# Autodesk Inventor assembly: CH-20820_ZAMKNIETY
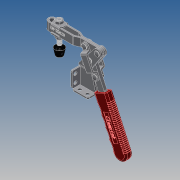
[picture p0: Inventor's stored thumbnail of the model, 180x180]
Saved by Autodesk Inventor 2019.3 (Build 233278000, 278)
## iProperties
Company: Î¢ÈíÖÐ¹ú
Created: 2011-12
Part Number: CH-20820_ZAMKNIETY
Material: Ogólny
Description: STEP AP203
Document SubType Name: Assembly
Designer: CADENGINEERING4
Sending System: SolidWorks 2010
Preprocessor: SwSTEP 2.0
Title: CH-20820.STEP
Author: Î¢ÈíÓÃ»§
Revision Number: ÈÎºÎ
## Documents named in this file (10)
- E:\STRONA\Horizontal toggle clamp\CH-20820\CH-20820_ZAMKNIETY.iam
- E:\STRONA\Horizontal toggle clamp\CH-20820\20820-02.ipt
- E:\STRONA\Horizontal toggle clamp\CH-20820\20820-06.ipt
- E:\STRONA\Horizontal toggle clamp\CH-20820\56212.ipt
- E:\STRONA\Horizontal toggle clamp\CH-20820\20820-03.ipt
- E:\STRONA\Horizontal toggle clamp\CH-20820\FW516.ipt
- E:\STRONA\Horizontal toggle clamp\CH-20820\20820-04.ipt
- E:\STRONA\Horizontal toggle clamp\CH-20820\CH-20820-05.ipt
- E:\STRONA\Horizontal toggle clamp\CH-20820\56212-02.ipt
- E:\STRONA\Horizontal toggle clamp\CH-20820\20820-01.ipt
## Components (15 placed, 15 different names)
1. 20820-02_1 — Zestawiające:1, Zestawiające:4, Zestawiające:6, Zestawiające:9, Zestawiające:24, Zestawiające:25, Zestawiające:28
2. 20820-06_2 — Zestawiające:22, Zestawiające:23
3. 56212_3 — Równoległe:1, Zestawiające:2, Zestawiające:5, Zestawiające:7, Zestawiające:9
4. 20820-06_4 — Zestawiające:28, Zestawiające:29, Zestawiające:30
5. 20820-03_5 — Zestawiające:10, Zestawiające:11, Zestawiające:12, Zestawiające:13, Zestawiające:14, Zestawiające:17, Zestawiające:18, Zestawiające:19, Zestawiające:20
6. FW516_6 — Równoległe:2, Zestawiające:5, Zestawiające:6, Zestawiające:8
7. 20820-04_7 — Zestawiające:19, Zestawiające:20, Zestawiające:21, Zestawiające:22, Zestawiające:23, Zestawiające:24, Zestawiające:25, Zestawiające:26, Zestawiające:27
8. CH-20820-05_8 — Zestawiające:10, Zestawiające:11, Zestawiające:12, Zestawiające:31
9. 56212-02_9 — Równoległe:1, Zestawiające:3
10. 20820-01_10 — Zestawiające:13, Zestawiające:14, Zestawiające:15, Zestawiające:16, Zestawiające:29, Zestawiające:30, Zestawiające:31
11. 20820-06_11 — Zestawiające:15, Zestawiające:16
12. 20820-06_12 — Zestawiające:26, Zestawiające:27
13. FW516_13 — Równoległe:2, Zestawiające:1, Zestawiające:2, Zestawiające:3, Zestawiające:4
14. 56212-02_14 — Zestawiające:7, Zestawiające:8
15. 20820-04_15 — Zestawiające:17, Zestawiające:18, Zestawiające:21
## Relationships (33: Mate 31, Flush 2)
- Równoległe:1 [Flush]: 56212_3 ↔ 56212-02_9
- Równoległe:2 [Flush]: FW516_6 ↔ FW516_13
- Zestawiające:1 [Mate]: 20820-02_1 ↔ FW516_13
- Zestawiające:2 [Mate]: 56212_3 ↔ FW516_13
- Zestawiające:3 [Mate]: 56212-02_9 ↔ FW516_13
- Zestawiające:4 [Mate]: 20820-02_1 ↔ FW516_13
- Zestawiające:5 [Mate]: 56212_3 ↔ FW516_6
- Zestawiające:6 [Mate]: 20820-02_1 ↔ FW516_6
- Zestawiające:7 [Mate]: 56212_3 ↔ 56212-02_14
- Zestawiające:8 [Mate]: FW516_6 ↔ 56212-02_14
- Zestawiające:9 [Mate]: 20820-02_1 ↔ 56212_3
- Zestawiające:10 [Mate]: 20820-03_5 ↔ CH-20820-05_8
- Zestawiające:11 [Mate]: 20820-03_5 ↔ CH-20820-05_8
- Zestawiające:12 [Mate]: 20820-03_5 ↔ CH-20820-05_8
- Zestawiające:13 [Mate]: 20820-03_5 ↔ 20820-01_10
- Zestawiające:14 [Mate]: 20820-03_5 ↔ 20820-01_10
- Zestawiające:15 [Mate]: 20820-01_10 ↔ 20820-06_11
- Zestawiające:16 [Mate]: 20820-01_10 ↔ 20820-06_11
- Zestawiające:17 [Mate]: 20820-03_5 ↔ 20820-04_15
- Zestawiające:18 [Mate]: 20820-03_5 ↔ 20820-04_15
- Zestawiające:19 [Mate]: 20820-03_5 ↔ 20820-04_7
- Zestawiające:20 [Mate]: 20820-03_5 ↔ 20820-04_7
- Zestawiające:21 [Mate]: 20820-04_7 ↔ 20820-04_15
- Zestawiające:22 [Mate]: 20820-06_2 ↔ 20820-04_7
- Zestawiające:23 [Mate]: 20820-06_2 ↔ 20820-04_7
- Zestawiające:24 [Mate]: 20820-02_1 ↔ 20820-04_7
- Zestawiające:25 [Mate]: 20820-02_1 ↔ 20820-04_7
- Zestawiające:26 [Mate]: 20820-04_7 ↔ 20820-06_12
- Zestawiające:27 [Mate]: 20820-04_7 ↔ 20820-06_12
- Zestawiające:28 [Mate]: 20820-02_1 ↔ 20820-06_4
- Zestawiające:29 [Mate]: 20820-06_4 ↔ 20820-01_10
- Zestawiające:30 [Mate]: 20820-06_4 ↔ 20820-01_10
- Zestawiające:31 [Mate]: CH-20820-05_8 ↔ 20820-01_10
